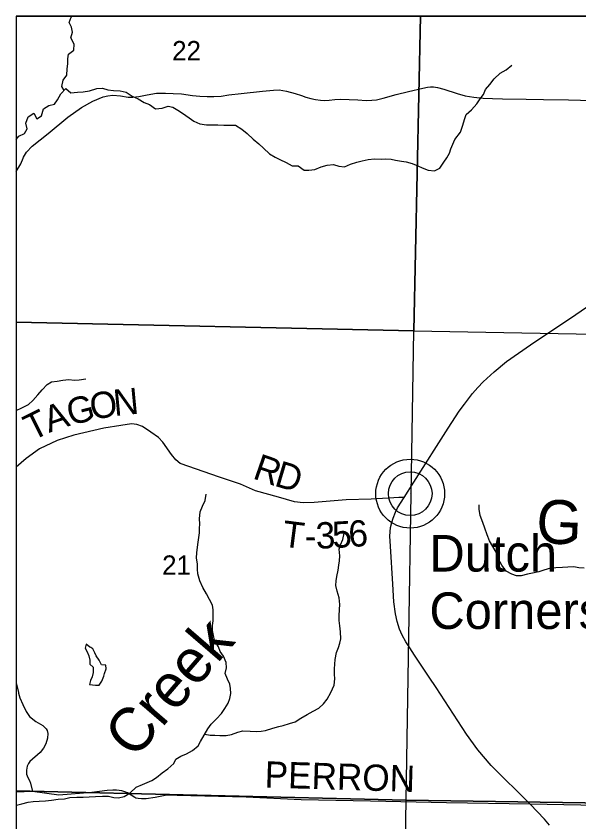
# Model space of a CAD drawing. Extents: x -3.6 to 34, y 0 to 32.8.
# Drawn here: x -3.63 to -2.413, y 31.101 to 32.843 of the extents above; entities that cross this region are included whole.
import ezdxf

# ---------------------------------------------------------------- set-up
doc = ezdxf.new("R2010")
doc.units = 0
for name, color, linetype in [('GM_X_Corporation', 7, 'Continuous'), ('GM_X_County_Road', 7, 'Continuous'), ('GM_X_Major_River', 7, 'Continuous'), ('GM_X_Minor_Lake', 7, 'Continuous'), ('GM_X_Minor_River', 7, 'Continuous'), ('GM_X_Minor_River_Text', 7, 'Continuous'), ('GM_X_Section_Text', 7, 'Continuous'), ('GM_X_State_Route', 7, 'Continuous'), ('GM_X_Township_Road', 7, 'Continuous'), ('GM_X_Township_Road_Text', 7, 'Continuous'), ('GM_X_Unincorporated', 7, 'Continuous'), ('GM_X_Unincorporated_Location', 7, 'Continuous'), ('GM_X_Unincorporated_Text', 7, 'Continuous'), ('SH_Data', 7, 'Continuous')]:
    doc.layers.add(name, color=color, linetype=linetype)

msp = doc.modelspace()

# ---------------------------------------------------------------- linework, layer by layer
at = {"layer": 'GM_X_Corporation'}
for points in [[(3.1705, 28.9337), (3.1705, 32.8429), (-3.6295, 32.8429), (-3.6295, 26.0429), (2.3706, 26.0429), (2.3712, 26.0804), (2.3716, 26.1248), (2.3732, 26.2253), (2.3789, 26.6097), (2.3911, 27.5117), (2.3952, 27.9336), (2.3997, 28.282), (2.4082, 28.9473), (2.5416, 28.945), (2.5837, 28.9442), (2.8343, 28.9397)], [(-2.7551, 32.8429), (-3.6295, 32.8429), (-3.6295, 32.1814), (-2.7692, 32.1629)], [(3.1705, 30.458), (3.1705, 32.8429), (-3.6295, 32.8429), (-3.6295, 30.6462), (-3.5736, 30.6453), (-2.8007, 30.6338), (-2.7027, 30.634), (-2.3541, 30.6318), (-0.5034, 30.5954), (-0.453, 30.5952), (-0.398, 30.5946), (0.2583, 30.5905), (0.2578, 30.5133), (0.3556, 30.5115), (0.4055, 30.5105), (1.2437, 30.4948), (1.7819, 30.4857), (3.0419, 30.4594)], [(-1.7439, 32.8429), (-2.7551, 32.8429), (-2.7692, 32.1629), (-1.7561, 32.1438)], [(-3.6295, 32.1814), (-3.6295, 31.1685), (-2.786, 31.1483), (-2.7692, 32.1629)], [(-2.7692, 32.1629), (-1.7561, 32.1438), (-1.7722, 31.1326), (-2.786, 31.1483)], [(-3.6295, 31.1685), (-3.6295, 30.1386), (-2.8032, 30.1329), (-2.786, 31.1483)], [(-1.7722, 31.1326), (-1.7886, 30.1145), (-2.8032, 30.1329), (-2.786, 31.1483)]]:
    msp.add_lwpolyline(points, close=True, dxfattribs=at)
at = {"layer": 'GM_X_County_Road'}
for points in [[(-3.6144, 32.5356), (-3.6133, 32.5382), (-3.607, 32.5486), (-3.5946, 32.5617), (-3.5603, 32.5894), (-3.5176, 32.6241), (-3.4882, 32.6456), (-3.4635, 32.6593), (-3.4412, 32.6684), (-3.4314, 32.6708), (-3.4207, 32.6718), (-3.4035, 32.6705), (-3.3873, 32.6678), (-3.3771, 32.668), (-3.3641, 32.6691), (-3.346, 32.6729), (-3.326, 32.6763), (-3.3064, 32.6765), (-3.29, 32.6759), (-3.2719, 32.6745), (-3.2483, 32.6716), (-3.232, 32.67), (-3.2165, 32.669), (-3.202, 32.6692), (-3.1862, 32.6698), (-3.1699, 32.6724), (-3.1429, 32.6759), (-3.0965, 32.6806), (-3.073, 32.6831), (-3.061, 32.6832), (-3.0448, 32.6807), (-3.0258, 32.6755), (-3.0124, 32.6714), (-3.003, 32.6678), (-2.9921, 32.6649), (-2.9819, 32.6625), (-2.9716, 32.6609), (-2.963, 32.6604), (-2.9528, 32.6615), (-2.9401, 32.6628), (-2.9288, 32.6633), (-2.9091, 32.6629), (-2.8903, 32.6617), (-2.8725, 32.6608), (-2.8606, 32.6611), (-2.8502, 32.6618), (-2.8362, 32.6654), (-2.8081, 32.6737), (-2.7814, 32.6799), (-2.7501, 32.6872), (-2.7403, 32.6892), (-2.7332, 32.69), (-2.727, 32.6897), (-2.7183, 32.6888), (-2.7048, 32.6849), (-2.6757, 32.6753), (-2.6589, 32.6708), (-2.6397, 32.6673), (-2.6194, 32.6655), (-2.5993, 32.6645), (-2.5775, 32.6638), (-2.527, 32.6634), (-2.4893, 32.6625), (-2.4353, 32.6616), (-2.3583, 32.6594)], [(-3.6295, 32.5068), (-3.6192, 32.5239), (-3.6144, 32.5356)]]:
    msp.add_lwpolyline(points, dxfattribs=at)
at = {"layer": 'GM_X_Major_River'}
msp.add_lwpolyline([(-3.6295, 32.5762), (-3.6234, 32.5831), (-3.6114, 32.589), (-3.6055, 32.5993), (-3.6084, 32.6118), (-3.6033, 32.6248), (-3.5909, 32.6333), (-3.585, 32.6205), (-3.5749, 32.6271), (-3.5703, 32.6424), (-3.559, 32.6494), (-3.5462, 32.6523), (-3.5403, 32.6618), (-3.5326, 32.6749), (-3.5218, 32.6864), (-3.5114, 32.6767), (-3.497, 32.6788), (-3.4842, 32.679), (-3.471, 32.6815), (-3.4548, 32.6863), (-3.4427, 32.6873), (-3.4309, 32.6833), (-3.4191, 32.6824), (-3.4047, 32.6815), (-3.3914, 32.6783), (-3.3788, 32.6697), (-3.3658, 32.6643), (-3.3528, 32.6561), (-3.341, 32.6518), (-3.328, 32.6421), (-3.314, 32.6439), (-3.3004, 32.6479), (-3.2905, 32.6461), (-3.2798, 32.6395), (-3.2695, 32.6328), (-3.255, 32.6232), (-3.2454, 32.6158), (-3.2324, 32.6099), (-3.218, 32.6075), (-3.1934, 32.6079), (-3.1805, 32.6073), (-3.1687, 32.6071), (-3.1555, 32.607), (-3.1414, 32.5988), (-3.1298, 32.5892), (-3.1171, 32.5772), (-3.1048, 32.5668), (-3.0948, 32.5575), (-3.0818, 32.5448), (-3.0692, 32.5382), (-3.0596, 32.5327), (-3.0455, 32.5261), (-3.0325, 32.5194), (-3.0196, 32.5193), (-3.007, 32.51), (-2.9967, 32.5098), (-2.9839, 32.5115), (-2.97, 32.5167), (-2.9572, 32.5203), (-2.9436, 32.5224), (-2.9314, 32.5188), (-2.9193, 32.5171), (-2.9065, 32.5226), (-2.8929, 32.527), (-2.8816, 32.5302), (-2.8684, 32.5331), (-2.8544, 32.5341), (-2.8404, 32.5339), (-2.8298, 32.5341), (-2.8188, 32.5335), (-2.8093, 32.5318), (-2.7961, 32.529), (-2.7858, 32.528), (-2.7733, 32.5244), (-2.7611, 32.5193), (-2.7515, 32.5149), (-2.7386, 32.5102), (-2.7249, 32.5081), (-2.7133, 32.5144), (-2.7048, 32.527), (-2.6981, 32.5366), (-2.6926, 32.5466), (-2.6894, 32.5561), (-2.6854, 32.5664), (-2.6806, 32.576), (-2.6688, 32.5917), (-2.6637, 32.6073), (-2.6598, 32.6195), (-2.6566, 32.6302), (-2.645, 32.6403), (-2.6335, 32.6533), (-2.6261, 32.6641), (-2.6191, 32.6737), (-2.6147, 32.684), (-2.6054, 32.6951), (-2.5958, 32.7074), (-2.5827, 32.7194), (-2.57, 32.7264), (-2.5577, 32.7369)], dxfattribs=at)
at = {"layer": 'GM_X_Minor_Lake'}
for points in [[(-3.4682, 31.4778), (-3.4701, 31.4789), (-3.4781, 31.4853), (-3.4803, 31.4769), (-3.4757, 31.4686), (-3.4722, 31.4603), (-3.4698, 31.4505), (-3.4704, 31.4422), (-3.4631, 31.4354), (-3.4626, 31.424), (-3.4648, 31.4149), (-3.4689, 31.4065), (-3.4706, 31.3978)], [(-3.4706, 31.3978), (-3.4578, 31.3968), (-3.4498, 31.3969), (-3.4439, 31.4053), (-3.4402, 31.416), (-3.4384, 31.4217), (-3.4347, 31.4319), (-3.4356, 31.4395), (-3.4447, 31.4402), (-3.4501, 31.4504), (-3.4563, 31.4601), (-3.459, 31.4666), (-3.4633, 31.4749), (-3.4682, 31.4778)]]:
    msp.add_lwpolyline(points, dxfattribs=at)
at = {"layer": 'GM_X_Minor_River'}
for points in [[(-3.5257, 32.6822), (-3.5306, 32.6906), (-3.5281, 32.7043), (-3.5196, 32.7151), (-3.5194, 32.7291), (-3.5177, 32.7397), (-3.5175, 32.7507), (-3.5161, 32.7606), (-3.5049, 32.7695), (-3.5039, 32.782), (-3.5113, 32.7956), (-3.5073, 32.8085), (-3.5101, 32.8191), (-3.5145, 32.8289), (-3.5108, 32.8407), (-3.5082, 32.8429)], [(-3.6295, 31.9901), (-3.6168, 31.9958), (-3.6029, 32.0032), (-3.5932, 32.0117), (-3.5828, 32.0243), (-3.5731, 32.0347), (-3.5627, 32.0466), (-3.5529, 32.052), (-3.5405, 32.0537), (-3.5284, 32.0562), (-3.5155, 32.0571), (-3.5034, 32.0561), (-3.4932, 32.0566), (-3.4789, 32.0591)], [(-3.2333, 31.7261), (-3.2331, 31.7356), (-3.2325, 31.7451), (-3.233, 31.7561), (-3.2317, 31.7712), (-3.2266, 31.7835), (-3.2207, 31.7961), (-3.2187, 31.8094)], [(-2.4884, 31.6454), (-2.4989, 31.6419), (-2.5129, 31.6386), (-2.5238, 31.6366), (-2.5377, 31.633), (-2.5476, 31.6328), (-2.5579, 31.6365), (-2.5697, 31.6432), (-2.579, 31.6563), (-2.5875, 31.6706), (-2.5918, 31.6838), (-2.5985, 31.6962), (-2.6058, 31.7086), (-2.6109, 31.7215), (-2.6161, 31.7358), (-2.6204, 31.7483), (-2.6263, 31.7637), (-2.628, 31.777), (-2.6285, 31.7864)], [(-3.6295, 31.1368), (-3.6287, 31.137), (-3.6174, 31.1398), (-3.6034, 31.1438), (-3.5928, 31.1451), (-3.5796, 31.146), (-3.566, 31.1466), (-3.5532, 31.1483), (-3.5384, 31.15), (-3.5248, 31.151), (-3.5135, 31.1538), (-3.4984, 31.1547), (-3.4844, 31.1545), (-3.4715, 31.1551), (-3.4576, 31.1561), (-3.4428, 31.1566), (-3.4296, 31.1568), (-3.4182, 31.1539), (-3.4083, 31.1533), (-3.3959, 31.1558), (-3.3828, 31.1639), (-3.3697, 31.1762), (-3.3562, 31.1821), (-3.3464, 31.186), (-3.3363, 31.1907), (-3.3258, 31.1973), (-3.3138, 31.2073), (-3.3014, 31.2155), (-3.2887, 31.227), (-3.284, 31.2369), (-3.2735, 31.2432), (-3.2611, 31.2479), (-3.2479, 31.2553), (-3.236, 31.2653), (-3.2308, 31.2748), (-3.2231, 31.2882), (-3.215, 31.3024), (-3.2079, 31.3123), (-3.1964, 31.3235), (-3.1856, 31.3354), (-3.1781, 31.3461), (-3.1708, 31.3576), (-3.1671, 31.3675), (-3.1654, 31.3789), (-3.1663, 31.3891), (-3.1672, 31.399), (-3.1723, 31.4099), (-3.1774, 31.4216), (-3.1749, 31.4338), (-3.1755, 31.4459), (-3.181, 31.4595), (-3.1883, 31.4692), (-3.1922, 31.4798), (-3.2004, 31.4941), (-3.2028, 31.5043), (-3.2052, 31.5149), (-3.205, 31.5259), (-3.2033, 31.5354), (-3.2036, 31.5596), (-3.2049, 31.5695), (-3.2111, 31.5815), (-3.2181, 31.5943), (-3.2259, 31.6075), (-3.2322, 31.6222), (-3.2365, 31.6369), (-3.2371, 31.6472), (-3.2376, 31.6582), (-3.2393, 31.6722), (-3.2384, 31.6824), (-3.2374, 31.6949), (-3.2361, 31.706), (-3.2347, 31.7158), (-3.2333, 31.7261)], [(-3.2218, 31.2905), (-3.2102, 31.2888), (-3.2, 31.2882), (-3.189, 31.2876), (-3.175, 31.2881), (-3.1637, 31.2902), (-3.1498, 31.2949), (-3.1396, 31.2977), (-3.1237, 31.2968), (-3.1101, 31.2966), (-3.0999, 31.2971), (-3.0901, 31.2988), (-3.0742, 31.3036), (-3.0618, 31.3071), (-3.052, 31.3092), (-3.0385, 31.3139), (-3.0264, 31.3175), (-3.014, 31.3252), (-3.0002, 31.3334), (-2.9874, 31.3404), (-2.975, 31.3466), (-2.9649, 31.3563), (-2.9568, 31.3666), (-2.949, 31.3808), (-2.9421, 31.3968), (-2.9404, 31.4105), (-2.9413, 31.4203), (-2.9411, 31.4317), (-2.9405, 31.4423), (-2.9399, 31.4518), (-2.9367, 31.4674), (-2.9327, 31.4777), (-2.9294, 31.4876), (-2.9273, 31.4971), (-2.9279, 31.5119), (-2.9296, 31.5251), (-2.9309, 31.5365), (-2.9307, 31.5467), (-2.9301, 31.56), (-2.9299, 31.571), (-2.9309, 31.5854), (-2.9352, 31.5998), (-2.9381, 31.6119), (-2.9375, 31.6221), (-2.9357, 31.6316), (-2.9329, 31.6453), (-2.9319, 31.6559), (-2.9302, 31.6654), (-2.9299, 31.6764), (-2.9309, 31.6905), (-2.928, 31.7), (-2.9233, 31.7118), (-2.9204, 31.7251)], [(-2.401, 31.6497), (-2.4128, 31.6503), (-2.4234, 31.6524), (-2.4366, 31.6518), (-2.448, 31.6513), (-2.4623, 31.65), (-2.4741, 31.6494), (-2.4884, 31.6454)]]:
    msp.add_lwpolyline(points, dxfattribs=at)
at = {"layer": 'GM_X_State_Route'}
msp.add_lwpolyline([(-2.4764, 31.0936), (-2.4869, 31.1069), (-2.5183, 31.1393), (-2.6023, 31.2226), (-2.6308, 31.2566), (-2.6559, 31.291), (-2.7211, 31.3914), (-2.7364, 31.4142), (-2.7682, 31.4617), (-2.7783, 31.4773), (-2.7869, 31.4905), (-2.7945, 31.5044), (-2.8004, 31.5174), (-2.8055, 31.5339), (-2.8089, 31.5509), (-2.8125, 31.5768), (-2.8149, 31.6152), (-2.8197, 31.6972), (-2.8211, 31.7189), (-2.8197, 31.7377), (-2.8171, 31.7484), (-2.8139, 31.7579), (-2.809, 31.7705), (-2.8045, 31.78), (-2.7904, 31.8024), (-2.7697, 31.8354), (-2.6954, 31.9519), (-2.6714, 31.9887), (-2.6603, 32.0039), (-2.6429, 32.0271), (-2.6313, 32.0403), (-2.6197, 32.0521), (-2.5959, 32.0742), (-2.569, 32.0966), (-2.5172, 32.1326), (-2.4194, 32.1979), (-2.3828, 32.2229)], dxfattribs=at)
at = {"layer": 'GM_X_Township_Road'}
msp.add_line((-3.6295, 31.4015), (-3.6246, 31.381), dxfattribs=at)
for points in [[(-2.7904, 31.8024), (-2.8018, 31.8024), (-2.8131, 31.8019), (-2.8621, 31.7985), (-2.9162, 31.7969), (-2.9849, 31.7917), (-3.0091, 31.7907), (-3.0277, 31.7932), (-3.0619, 31.803), (-3.1122, 31.8165), (-3.1441, 31.8312), (-3.1896, 31.8464), (-3.2745, 31.8758), (-3.2844, 31.8836), (-3.2933, 31.8949), (-3.3123, 31.9216), (-3.3219, 31.9318), (-3.338, 31.9437), (-3.356, 31.9557), (-3.3686, 31.9604), (-3.3797, 31.9614), (-3.4028, 31.9581), (-3.4396, 31.952), (-3.5048, 31.9367), (-3.5404, 31.9257), (-3.5793, 31.9073), (-3.6079, 31.8865), (-3.6295, 31.8681)], [(-3.6246, 31.381), (-3.6242, 31.3791), (-3.6217, 31.3689), (-3.6147, 31.3546), (-3.6081, 31.3395), (-3.6003, 31.3289), (-3.5869, 31.3181), (-3.572, 31.3095), (-3.5687, 31.3067), (-3.5646, 31.3024), (-3.5626, 31.2986), (-3.5607, 31.2918), (-3.562, 31.2818), (-3.565, 31.2701), (-3.5704, 31.2606), (-3.5777, 31.2509), (-3.5995, 31.2317), (-3.6024, 31.2276), (-3.6057, 31.2212), (-3.6074, 31.2128), (-3.6071, 31.2042), (-3.6044, 31.1967), (-3.6005, 31.1907), (-3.5983, 31.1846), (-3.5938, 31.1664)], [(-2.5183, 31.1393), (-2.6991, 31.1422), (-2.8633, 31.1459), (-3.0135, 31.1489), (-3.1322, 31.1543), (-3.2812, 31.1578), (-3.3036, 31.1586), (-3.3287, 31.1541), (-3.348, 31.1512), (-3.3583, 31.1507), (-3.3655, 31.1515), (-3.3704, 31.1526), (-3.3731, 31.1536), (-3.3889, 31.164), (-3.3943, 31.1662), (-3.4011, 31.168), (-3.4125, 31.1698), (-3.4206, 31.1697), (-3.4326, 31.1692), (-3.466, 31.1646), (-3.5374, 31.1591), (-3.5938, 31.1664), (-3.6295, 31.1653)], [(-1.9582, 31.1314), (-1.9654, 31.1338), (-1.9941, 31.1435), (-2.0427, 31.1433), (-2.2262, 31.1334), (-2.5183, 31.1393)]]:
    msp.add_lwpolyline(points, dxfattribs=at)
at = {"layer": 'GM_X_Unincorporated'}
for radius in [0.0744, 0.0472]:
    msp.add_circle((-2.7774, 31.8106), radius, dxfattribs=at)
at = {"layer": 'GM_X_Unincorporated_Location'}
msp.add_line((-2.7774, 31.8106), (-2.7774, 31.8106), dxfattribs=at)
at = {"layer": 'SH_Data'}
for q in [(-3.6295, 26.0429), (3.1705, 32.8429)]:
    msp.add_line((-3.6295, 32.8429), q, dxfattribs=at)

# ---------------------------------------------------------------- texts
at = {"layer": 'GM_X_Minor_River_Text'}
for s, height, rotation, p in [('G', 0.0947, 357.544, (-2.5063, 31.704)), ('Creek', 0.09469, 49.2255, (-3.374, 31.2341))]:
    msp.add_text(s, height=height, rotation=rotation, dxfattribs=at).set_placement(p)
at = {"layer": 'GM_X_Section_Text'}
for s, p in [('22', (-3.2921, 32.7472)), ('21', (-3.3138, 31.6352))]:
    msp.add_text(s, height=0.04186, rotation=0, dxfattribs=at).set_placement(p)
at = {"layer": 'GM_X_Township_Road_Text'}
for s, height, rotation, p in [('O', 0.0568, 10.7656, (-3.4646, 31.9693)), ('N', 0.0568, 5.3717, (-3.4169, 31.9784)), ('G', 0.0568, 14.0106, (-3.5123, 31.9574)), ('A', 0.0568, 18.716, (-3.5585, 31.9417)), ('T', 0.0568, 26.4347, (-3.5947, 31.9235)), ('R', 0.0568, 340.8615, (-3.1201, 31.8442)), ('D', 0.0568, 343.4279, (-3.0734, 31.8281)), ('6', 0.0568, 3.6317, (-2.9093, 31.6949)), ('T', 0.0568, 352.7724, (-3.0564, 31.6966)), ('3', 0.0568, 2.4012, (-2.9806, 31.6913)), ('5', 0.0568, 3.3547, (-2.9446, 31.6929)), ('-', 0.0568, 1.4021, (-3.005, 31.6907)), ('PERRON', 0.05682, 358.2813, (-3.0927, 31.1754))]:
    msp.add_text(s, height=height, rotation=rotation, dxfattribs=at).set_placement(p)
at = {"layer": 'GM_X_Unincorporated_Text'}
for s, p in [('Dutch', (-2.7358, 31.6422)), ('Corners', (-2.7358, 31.5181))]:
    msp.add_text(s, height=0.07898, rotation=0, dxfattribs=at).set_placement(p)

doc.saveas('drawing.dxf')
